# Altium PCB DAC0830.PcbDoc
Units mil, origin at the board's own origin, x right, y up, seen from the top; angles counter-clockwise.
Board outline 6000 x 4000 mil, 2 copper layers (Top Layer, Bottom Layer); 11 components, 23 nets, 59 pads, 17 vias.
Unrouted connection lines stored in the file: 1.
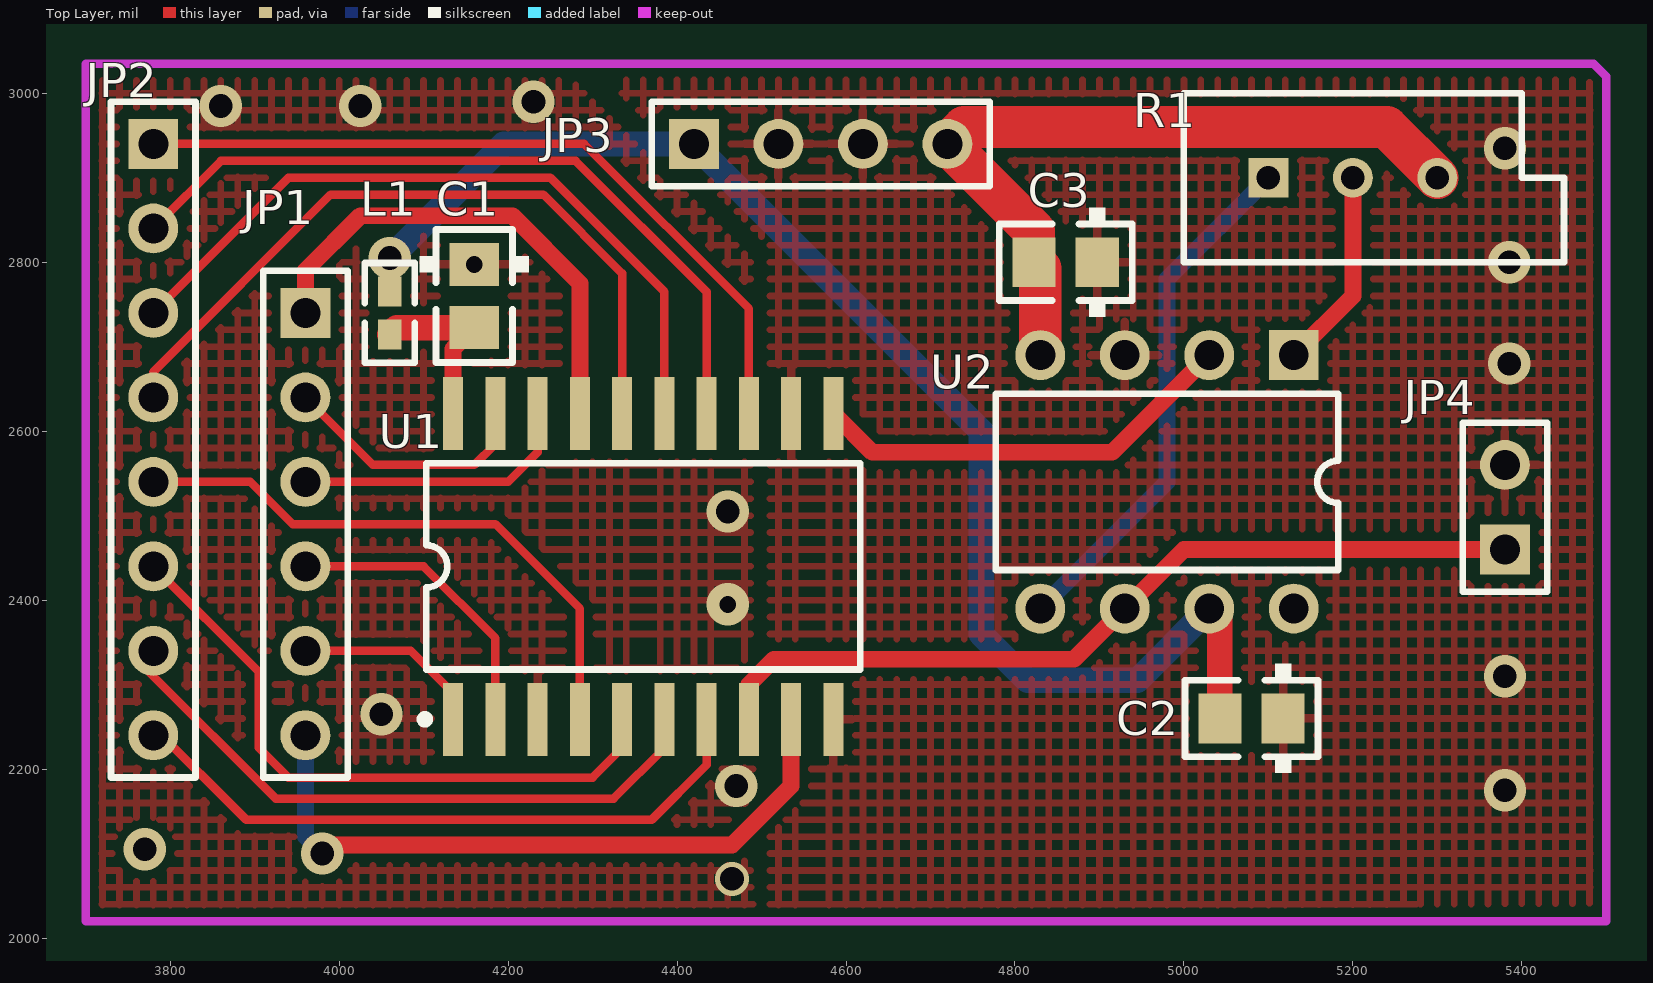
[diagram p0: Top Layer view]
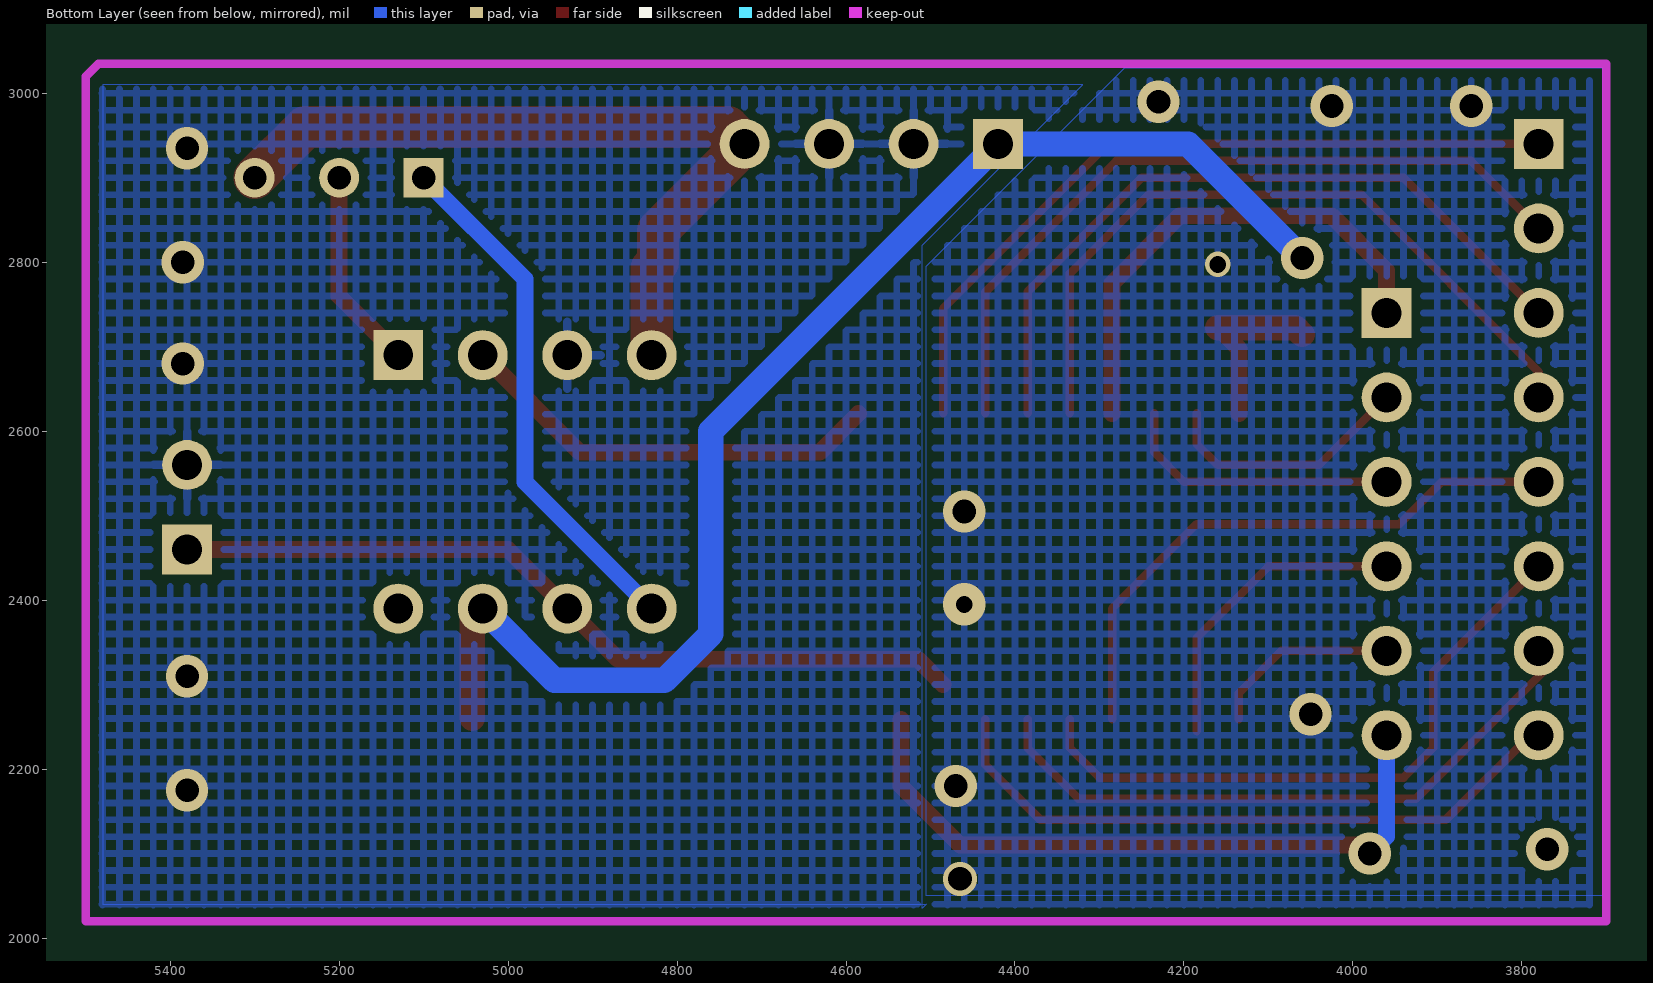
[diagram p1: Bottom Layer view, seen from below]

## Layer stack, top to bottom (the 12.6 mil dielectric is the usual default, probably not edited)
Top Layer: signal copper 1.4
Dielectric: dielectric 12.6, FR-4, Dk 4.8
Bottom Layer: signal copper 1.4

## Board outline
1000,1000 7000,1000 7000,5000 1000,5000

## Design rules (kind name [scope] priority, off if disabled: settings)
Clearance [All] p1: gap=10
ComponentClearance [All] p1: gap=10 collisioncheckmode=0
PolygonConnect [All] p1: connectstyle=Relief reliefconductorwidth=10 reliefentries=4 polygonreliefangle="90 Angle"
RoutingLayers [All] p1: top layer=Horizontal bottom layer=Vertical
RoutingVias [All] p1: holewidth=28 width=50 viastyle="Through Hole" minholewidth=28 minwidth=50 maxholewidth=28 maxwidth=50
SolderMaskExpansion [All] p1: expansion=4
TestPointUsage [All] p1: valid=0 allowmultiple=FALSE
Testpoint [All] p1: side=15 testpointundercomponent=TRUE minsize=40 maxsize=100 preferedsize=60 minholesize=0 maxholesize=40 preferedholesize=32 testpointgrid=1 style=1023 order=-539222988
Width [All] p1: maxlimit=50 minlimit=10 preferedwidth=20 toplayer_prefwidth=30 bottomlayer_prefwidth=30 minimp=50.000000 maximp=50.000000 favimp=50.000000
16 further rules are at their usual default settings.

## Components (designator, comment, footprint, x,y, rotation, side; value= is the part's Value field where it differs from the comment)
C1 "100pF" CC2012-0805 4160,2760 r270 top
C2 "100pF" CC2012-0805 5080,2260 r180 top
C3 "100pF" CC2012-0805 4860,2800 r180 top
JP1 "Header 6" HDR1X6 3960,2740 r270 top
JP2 "Header 8" HDR1X8 3780,2940 r270 top
JP3 "Header 4" HDR1X4 4420,2940 r0 top
JP4 "Header 2" HDR1X2 5380,2460 r90 top
L1 "Inductor" C1005-0402 4060,2740 r90 top
R1 "10K" VR5 5200,2900 r0 top
U1 "DAC0830LCM" SO-G20 4360,2440 r0 top
U2 "LF351N" DIP-8 4980,2540 r180 top

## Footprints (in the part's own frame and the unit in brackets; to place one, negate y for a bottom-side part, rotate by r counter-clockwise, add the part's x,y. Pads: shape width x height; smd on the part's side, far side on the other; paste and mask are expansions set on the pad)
C1005-0402 [mm]
  rect 0.9x0.7 smd: 1(-0.65,0) 2(0.65,0)
  silkscreen extent -1.5,-0.75 1.5,0.75
CC2012-0805 [mm]
  rect 1.3x1.5 smd: 1(-0.95,0) 2(0.95,0)
  silkscreen extent -2,-1.65 2,1.64
DIP-8 [mm]
  rect 1.5x1.5 hole 0.9: 1(-3.81,-3.81)
  round 1.5 hole 0.9: 2(-1.27,-3.81) 3(1.27,-3.81) 4(3.81,-3.81) 5(3.81,3.81) 6(1.27,3.81) 7(-1.27,3.81) 8(-3.81,3.81)
  silkscreen extent -5.15,-2.65 5.15,2.65
HDR1X2 [mm]
  rect 1.5x1.5 hole 0.9: 1(0,0)
  round 1.5 hole 0.9: 2(2.54,0)
  silkscreen extent -1.27,-1.27 3.81,1.27
HDR1X4 [mm]
  rect 1.5x1.5 hole 0.9: 1(0,0)
  round 1.5 hole 0.9: 2(2.54,0) 3(5.08,0) 4(7.62,0)
  silkscreen extent -1.27,-1.27 8.89,1.27
HDR1X6 [mm]
  rect 1.5x1.5 hole 0.9: 1(0,0)
  round 1.5 hole 0.9: 2(2.54,0) 3(5.08,0) 4(7.62,0) 5(10.16,0) 6(12.7,0)
  silkscreen extent -1.27,-1.27 13.97,1.27
HDR1X8 [mm]
  rect 1.5x1.5 hole 0.9: 1(0,0)
  round 1.5 hole 0.9: 2(2.54,0) 3(5.08,0) 4(7.62,0) 5(10.16,0) 6(12.7,0) 7(15.24,0) 8(17.78,0)
  silkscreen extent -1.27,-1.27 19.05,1.27
SO-G20 [mm]
  rect 0.6x2.2 smd: 1(-5.715,-4.6) 2(-4.445,-4.6) 3(-3.175,-4.6) 4(-1.905,-4.6) 5(-0.635,-4.6) 6(0.635,-4.6) 7(1.905,-4.6) 8(3.175,-4.6) 9(4.445,-4.6) 10(5.715,-4.6) 11(5.715,4.6) 12(4.445,4.6) 13(3.175,4.6) 14(1.905,4.6) 15(0.635,4.6) 16(-0.635,4.6) 17(-1.905,4.6) 18(-3.175,4.6) 19(-4.445,4.6) 20(-5.715,4.6)
  silkscreen extent -6.69,-4.72 6.53,3.1
VR5 [mm]
  rect 1.2x1.2 hole 0.7: 1(-2.54,0)
  round 1.2 hole 0.7: 2(0,0) 3(2.54,0)
  silkscreen extent -5.08,-2.54 6.35,2.54

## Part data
C1 C2 C3: library part Cap, "Capacitor"
JP1: "Header, 6-Pin"
JP2: "Header, 8-Pin"
JP3: "Header, 4-Pin"
JP4: "Header, 2-Pin"
R1: library part RPot2, "Potentiometer"
U1: "8-Bit 礟-Compatible, Double-Buffered Digital-to-Analog Converter"
U2: "Wide-Bandwidth JFET Input Operational Amplifier"

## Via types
v1: diameter 50, hole 28, Top Layer to Bottom Layer, 14 vias
v2: diameter 30, hole 20, Top Layer to Bottom Layer, 1 vias
v3: diameter 50, hole 20, Top Layer to Bottom Layer, 1 vias
v4: diameter 40, hole 28, Top Layer to Bottom Layer, 1 vias

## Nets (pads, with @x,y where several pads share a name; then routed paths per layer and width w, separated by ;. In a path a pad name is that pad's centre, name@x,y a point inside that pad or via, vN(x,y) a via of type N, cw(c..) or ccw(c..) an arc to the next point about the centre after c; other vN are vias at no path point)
+15V: C2.2 JP3.1 L1.2 U2.7 | length 1600
  Top Layer w30: U2.7 5042.6,2377.4 C2.2
  Bottom Layer w30: v1(4060,2805) 4195,2940 JP3.1 4760,2600 4760,2360 4815,2305 4945,2305 U2.7
-15V: C3.2 JP3.4 R1.3 U2.4 | length 908.7
  Top Layer w50: U2.4 4830,2792.6 C3.2 4822.6,2837.4 JP3.4 4740,2960 5240,2960 R1.3
DGND: C1.1 U1.3
  other v1: 4470,2180 4050,2265 4460,2505 3860,2985 4025,2985 4230,2990
  other v2: 4160,2797.4
  other v3: 4460,2395
  other v4: 4465,2070
GND: C2.1 C3.1 JP3.2 JP3.3 JP4.2 U1.10 U1.12 U2.3
  other v1: 5380,2175 5380,2310 5385,2680 5385,2800 5380,2935
NetC1_2: C1.2 L1.1 U1.20 | length 215.2
  Top Layer w20: U1.20 4135,2697.6 C1.2
  Top Layer w30: L1.1 4068.19,2722.6 C1.2
NetJP1_1: JP1.1 U1.17 | length 589
  Top Layer w20: JP1.1 3960,2790 4025,2855 4205,2855 4285,2775 U1.17
NetJP1_2: JP1.2 U1.19 | length 304.6
  Top Layer w10: JP1.2 4040,2560 4160,2560 4185,2585 U1.19
NetJP1_3: JP1.3 U1.18 | length 335.6
  Top Layer w10: JP1.3 4200,2540 4235,2575 U1.18
NetJP1_4: JP1.4 U1.2 | length 370.2
  Top Layer w10: JP1.4 4100,2440 4185,2355 U1.2@4185,2245
NetJP1_5: JP1.5 U1.1 | length 226.8
  Top Layer w10: JP1.5 4085,2340 4135,2290 U1.1
NetJP2_1: JP2.1 U1.13 | length 909.7
  Top Layer w10: JP2.1 4290,2940 4485,2745 U1.13
NetJP2_2: JP2.2 U1.14 | length 896.2
  Top Layer w10: JP2.2 3860,2920 4280,2920 4435,2765 U1.14
NetJP2_3: JP2.3 U1.15 | length 871.1
  Top Layer w10: JP2.3 3940,2900 4250,2900 4385,2765 U1.15
NetJP2_4: JP2.4 U1.16 | length 876.2
  Top Layer w10: JP2.4 3780,2670 3990,2880 4241.72,2880 4335,2786.72 U1.16
NetJP2_5: JP2.5 U1.4 | length 698.2
  Top Layer w10: JP2.5 3895,2540 3945,2490 4185,2490 4285,2390 U1.4
NetJP2_6: JP2.6 U1.5 | length 759.7
  Top Layer w10: JP2.6 3905,2315 3905,2225 3940,2190 4300,2190 4335,2225 U1.5
NetJP2_7: JP2.7 U1.6 | length 765.9
  Top Layer w10: JP2.7@3775,2350 3775,2315 3925,2165 4325,2165 4385,2225 U1.6
NetJP2_8: JP2.8 U1.7 | length 781.4
  Top Layer w10: JP2.8@3780,2250 3890,2140 4370,2140 4435,2205 U1.7
NetJP4_1: JP4.1 U1.8 U2.6 | length 961.3
  Top Layer w20: U1.8@4485,2300 4515,2330 4870,2330 5000,2460 JP4.1
NetR1_1: R1.1 U2.5 | length 621.8
  Bottom Layer w20: U2.5 4980,2540 4980,2780 R1.1
NetR1_2: R1.2 U2.1 | length 239
  Top Layer w20: U2.1 5200,2760 R1.2
NetU1_11: U1.11 U2.2 | length 511.7
  Top Layer w20: U1.11 4631.1,2575 4915,2575 U2.2
VIN: JP1.6 U1.9 | length 816.2
  Top Layer w20: v1@3975,2110 4465,2110 4535,2180 U1.9
  Bottom Layer w20: JP1.6 3960,2120 v1(3980,2100)
pads on no net: U2.8
copper on no net:
  other v1: 3770,2105

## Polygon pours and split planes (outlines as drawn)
GND on Top Layer (hatched 90Degree grid 20 track 8, remove dead copper): 4510,2036 4510,2820.12 4315,3020 5490,3020 5490,2041.12
DGND on Top Layer (hatched 90Degree grid 20 track 8, remove dead copper): 4490,2030 4490,2800 4275,3015 3705,3015 3705,2035 4490,2035
DGND on Bottom Layer (hatched 90Degree grid 20 track 8, remove dead copper): 4505,2050 4505,2795 4270,3030 3705,3030 3705,2050
DGND on Bottom Layer (hatched 90Degree grid 20 track 8, remove dead copper): 4495,2030 4495,2805 4285,3015 3720,3015 3720,2030
DGND on Bottom Layer (hatched 90Degree grid 20 track 8, remove dead copper): 4510,2035 4510,2820 4320,3010 5480,3010 5480,2040 4505,2040
GND on Bottom Layer (hatched 90Degree grid 20 track 8, remove dead copper): 4515,2040 4515,2815 4325,3005 5495,3005 5495,2035 4510,2035

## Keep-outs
Keep-Out Layer:
  lines w10: 3700,2020 3700,3035 5485,3035 5500,3020 5500,2020 3700,2020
